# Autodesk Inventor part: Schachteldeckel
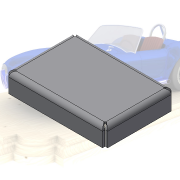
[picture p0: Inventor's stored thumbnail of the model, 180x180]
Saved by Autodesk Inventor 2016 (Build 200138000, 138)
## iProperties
Created: 2015-05
Part Number: Schachteldeckel
Material: Generisch
Document SubType Name: Sheet Metal
Designer: thomas
Density: 1 g/cm^3
Flat Pattern Width: 13.0572 cm
Flat Pattern Length: 17.0572 cm
Flat Pattern Area: 222.718 cm^2
Sheet Metal Rule: Standard_mm
Sheet Metal Width: 130,572 mm
Sheet Metal Length: 170,572 mm
Sheet Metal Area: 22271,831 mm^2
Appearance: Vorgabe
Author: thomas
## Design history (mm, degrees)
derived "Schachtel.ipt"
feature "Volumenkörper2::Schachtel.ipt" dims "d0" = 10
tag "Bezeichnung1"
node "Volumenkörper1"
feature "Definition1"
other parameters: "Thickness" = 3 (derived), "BendRadius" = 3 (= Thickness), "BendReliefWidth" = 3 (= Thickness), "BendReliefDepth" = 1.5 (= 0.5 x Thickness), "CornerReliefSize" = 12 (= 4 x Thickness), "SeamGap" = 0.01, "MinimumRemnant" = 6 (= 2 x Thickness), "TransitionRadius" = 3 (= BendRadius), "JacobiRadiusSize" = 3 (= BendRadius), "GapSize" = 1.5 (= 0.5 x Thickness), "BendRadius" = 3, "BendReliefDepth" = 1.5, "BendReliefWidth" = 3, "CornerReliefSize" = 12, "GapSize" = 1.5, "JacobiRadiusSize" = 3, "MinimumRemnant" = 6, "Thickness" = 3, "TransitionRadius" = 3
